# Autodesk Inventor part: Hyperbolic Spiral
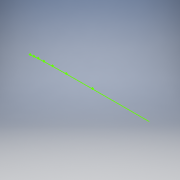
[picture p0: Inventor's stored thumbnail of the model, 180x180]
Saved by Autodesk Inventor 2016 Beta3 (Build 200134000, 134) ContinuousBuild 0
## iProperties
Created: 2008-02
Part Number: Hyperbolic Spiral
Document SubType Name: Modeling
Designer: Autodesk, Inc.
Density: 1 g/cm^3
Material: Generic
Appearance: Default
Author: Autodesk, Inc.
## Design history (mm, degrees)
sketch "Sketch1"
  geometry: 300 further points
  constraints: 300 other
